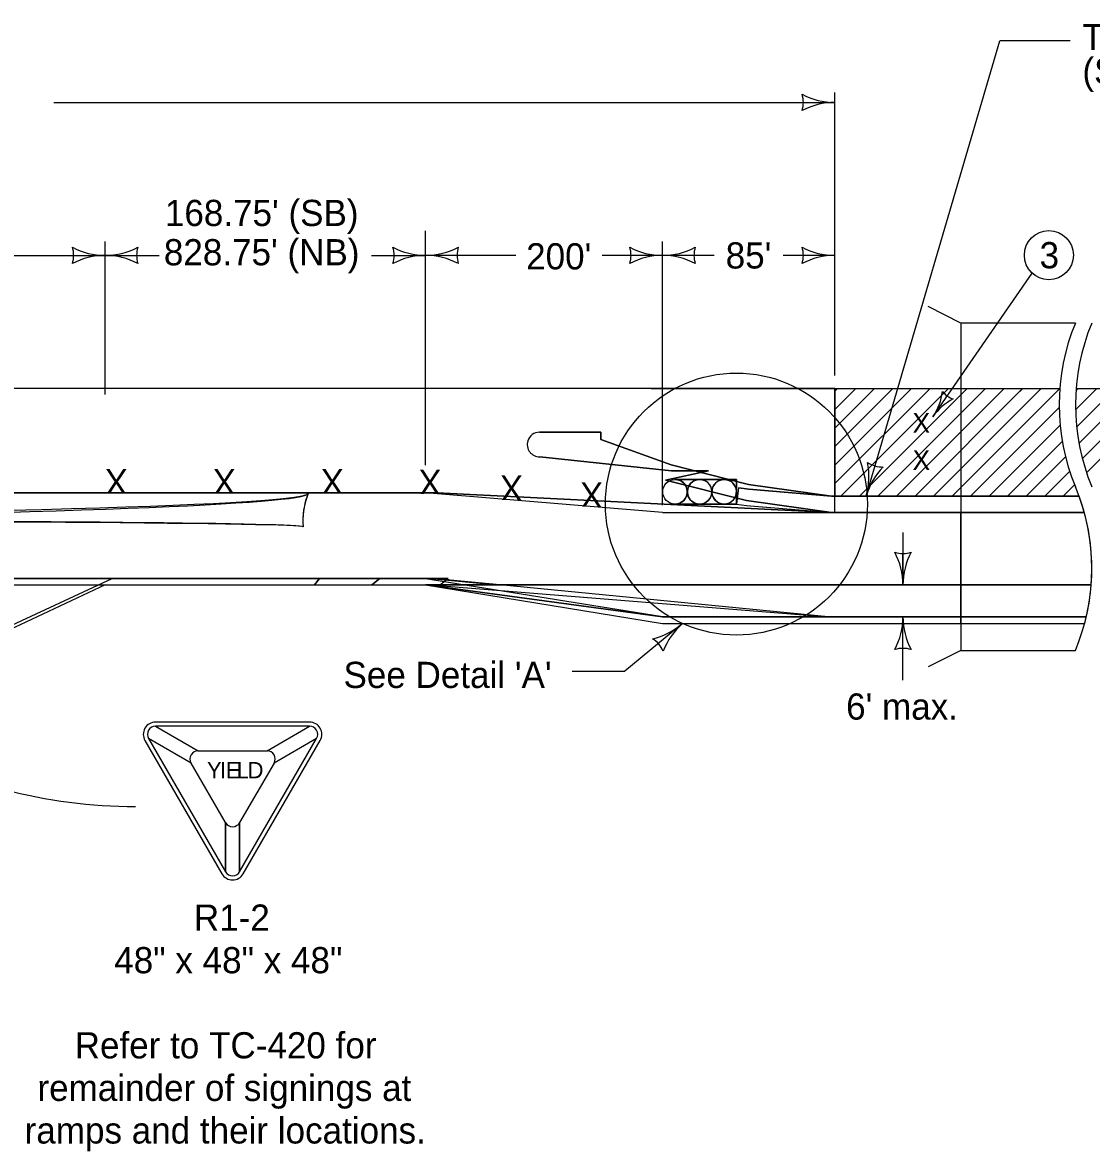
# Model space of a CAD drawing. Extents: x 10134 to 13311, y 7934 to 9733.
# Drawn here: x 12036 to 12689, y 8897 to 9587 of the extents above; entities that cross this region are included whole.
import ezdxf

# ---------------------------------------------------------------- set-up
doc = ezdxf.new("R2010")
doc.units = 0
for name, color, linetype in [('dsnCellElements', 7, 'Continuous'), ('dsnNonPlotable', 7, 'Continuous'), ('dsnstdModifiedBlock', 7, 'Continuous'), ('dsnStdNote', 7, 'Continuous'), ('dsnStdShading', 7, 'Continuous'), ('SheetText', 7, 'Continuous')]:
    doc.layers.add(name, color=color, linetype=linetype)

# ---------------------------------------------------------------- blocks, each defined once
blk = doc.blocks.new('LT')
at = {"layer": 'dsnCellElements'}
for centre, radius, start, end in [((-3.564, 0), 1.642, 342.26665, 17.73335), ((0, 4.25), 4.25, 241.92751, 270), ((0, -4.25), 4.25, 90, 118.07249)]:
    blk.add_arc(centre, radius, start, end, dxfattribs=at)

msp = doc.modelspace()

# ---------------------------------------------------------------- linework, layer by layer
at = {"layer": 'dsnCellElements'}
for p, q in [((12532.42, 9363.04), (12532.42, 9297.31)), ((12532.42, 9316.23), (12579.23, 9363.04)), ((12532.42, 9304.92), (12590.54, 9363.04)), ((12532.42, 9361.48), (12533.97, 9363.04)), ((12532.42, 9350.17), (12545.29, 9363.04)), ((12532.42, 9338.86), (12556.6, 9363.04)), ((12532.42, 9327.54), (12567.91, 9363.04)), ((12536.12, 9297.31), (12601.85, 9363.04)), ((12547.43, 9297.31), (12613.17, 9363.04)), ((12558.75, 9297.31), (12624.48, 9363.04)), ((12570.06, 9297.31), (12635.8, 9363.04)), ((12581.38, 9297.31), (12647.11, 9363.04)), ((12592.69, 9297.31), (12658.42, 9363.04)), ((12643.19, 9359.08), (12647.15, 9363.04)), ((12643.97, 9337.27), (12669.74, 9363.04)), ((12679.39, 9350.06), (12692.36, 9363.04)), ((12679.63, 9361.63), (12681.05, 9363.04)), ((12680.07, 9339.43), (12703.68, 9363.04)), ((12681.49, 9329.54), (12714.99, 9363.04)), ((12683.55, 9320.28), (12726.31, 9363.04)), ((12686.14, 9311.57), (12737.62, 9363.04)), ((12615.32, 9297.31), (12669.36, 9351.36)), ((12604, 9297.31), (12643.97, 9337.27)), ((12626.63, 9297.31), (12669.95, 9340.62)), ((12637.94, 9297.31), (12671.29, 9330.66)), ((12649.26, 9297.31), (12673.28, 9321.33)), ((12660.57, 9297.31), (12675.82, 9312.55)), ((12671.89, 9297.31), (12678.85, 9304.27)), ((12427.15, 9223.54), (12281.29, 9247.02)), ((12211.62, 9159.28), (12117.6, 9159.28)), ((12111.1, 9148.03), (12158.11, 9066.6)), ((12171.1, 9066.6), (12218.11, 9148.03)), ((12160.28, 9097.85), (12160.28, 9067.85)), ((12168.94, 9067.85), (12168.94, 9097.85))]:
    msp.add_line(p, q, dxfattribs=at)
for points in [[(12211.62, 9156.78), (12117.6, 9156.78), (12143.58, 9141.78), (12185.64, 9141.78), (12211.62, 9156.78)], [(12113.27, 9149.28), (12160.28, 9067.85), (12160.28, 9097.85), (12139.25, 9134.28), (12113.27, 9149.28)], [(12168.94, 9067.85), (12215.95, 9149.28), (12189.97, 9134.28), (12168.94, 9097.85), (12168.94, 9067.85)]]:
    msp.add_lwpolyline(points, close=True, dxfattribs=at)
for centre in [(12434.8, 9299.95), (12449.81, 9299.95), (12464.81, 9299.95)]:
    msp.add_circle(centre, 7.5, dxfattribs=at)
for centre, radius, start, end in [((12117.6, 9151.78), 7.5, 90.00021, 209.99992), ((12211.62, 9151.78), 7.5, 330.0002, 89.99991), ((12117.6, 9151.78), 5, 89.99991, 210.00019), ((12117.6, 9151.78), 5, 89.99991, 210.00019), ((12211.62, 9151.78), 5, 330.0002, 89.99991), ((12211.62, 9151.78), 5, 330.0002, 89.99991), ((12143.58, 9136.78), 5, 90.00021, 209.99992), ((12143.58, 9136.78), 5, 90.00021, 209.99992), ((12185.64, 9136.78), 5, 330.0002, 89.99991), ((12185.64, 9136.78), 5, 330.0002, 89.99991), ((12164.61, 9100.35), 5, 209.99992, 330.0002), ((12164.61, 9070.35), 5, 210.00019, 330.00161), ((12164.61, 9070.35), 7.5, 209.99992, 330.0002)]:
    msp.add_arc(centre, radius, start, end, dxfattribs=at)
at = {"layer": 'dsnNonPlotable'}
for p, q in [((12434.8, 9307.45), (12472.31, 9307.45)), ((12472.31, 9307.45), (12472.31, 9292.44)), ((12472.31, 9292.44), (12434.8, 9292.44))]:
    msp.add_line(p, q, dxfattribs=at)
for centre in [(12434.8, 9299.95), (12434.8, 9299.95), (12449.81, 9299.95), (12449.81, 9299.95), (12464.81, 9299.95), (12464.81, 9299.95)]:
    msp.add_circle(centre, 7.5, dxfattribs=at)
at = {"layer": 'dsnstdModifiedBlock'}
for p, q in [((12609.35, 9403.04), (12589.35, 9413.04)), ((11624.65, 9299.31), (12282.39, 9299.31)), ((12427.15, 9287.31), (12282.39, 9299.31)), ((12530.46, 9297.31), (12681.58, 9297.31)), ((12427.15, 9287.31), (12530.46, 9287.31)), ((12684.75, 9287.31), (12530.46, 9287.31)), ((12091.18, 9247.02), (12281.29, 9247.02)), ((12282.49, 9243.04), (12511.31, 9243.04)), ((12511.31, 9243.04), (12688.97, 9243.04)), ((12427.15, 9223.54), (12685.96, 9223.54)), ((12609.35, 9203.04), (12589.35, 9193.04))]:
    msp.add_line(p, q, dxfattribs=at)
for points in [[(12679.35, 9403.04), (12609.35, 9403.04), (12609.35, 9203.04), (12679.35, 9203.04)], [(12473.58, 9302.29), (12472.31, 9292.44), (12472.31, 9292.44)], [(12473.58, 9302.29), (12479.81, 9301.48), (12530.46, 9297.31)], [(12472.31, 9292.44), (12478.54, 9291.64), (12530.46, 9287.31)], [(11663.8, 9047.24), (11864.09, 9141.44), (12091.18, 9247.02)]]:
    msp.add_lwpolyline(points, dxfattribs=at)
for centre, start, end in [((12799.35, 9353.04), 157.38014, 202.61987), ((12809.35, 9353.04), 157.38014, 202.61987), ((12559.35, 9253.04), 337.38014, 22.61987)]:
    msp.add_arc(centre, 130, start, end, dxfattribs=at)
at = {"layer": 'dsnStdNote'}
msp.add_circle((12663.15, 9444.45), 15, dxfattribs=at)
at = {"layer": 'dsnStdShading'}
for p, q in [((12420.28, 9363.04), (11205.92, 9363.04)), ((12420.28, 9363.04), (12669.74, 9363.04)), ((12679.74, 9363.04), (13246.66, 9363.04)), ((12532.42, 9338.86), (12532.42, 9350.17)), ((12389.57, 9331.96), (12389.57, 9336.32)), ((12432.66, 9312.8), (12352.18, 9321.32)), ((12352.18, 9321.32), (12432.66, 9312.8)), ((12532.42, 9304.92), (12532.42, 9316.23)), ((12447.68, 9312.8), (12432.93, 9312.8)), ((12432.93, 9312.8), (12447.68, 9312.8)), ((12455.3, 9312.8), (12447.92, 9312.8)), ((12447.92, 9312.8), (12455.3, 9312.8)), ((12449.42, 9307.46), (12434.82, 9307.46)), ((12464.43, 9307.46), (12449.43, 9307.46)), ((12472.33, 9307.46), (12464.43, 9307.46)), ((12473.58, 9302.29), (12472.31, 9292.44)), ((12472.33, 9300.35), (12472.33, 9307.46)), ((12532.42, 9297.31), (12532.42, 9304.92)), ((11727.95, 9299.31), (12256.6, 9299.31)), ((12289.4, 9299.31), (11727.95, 9299.31)), ((12210.81, 9298.9), (12210.21, 9297.37)), ((12256.61, 9299.31), (12289.4, 9299.31)), ((12289.4, 9299.31), (12530.46, 9287.31)), ((12530.46, 9287.31), (12289.4, 9299.31)), ((12472.33, 9292.46), (12472.33, 9299.96)), ((12681.58, 9297.31), (12530.46, 9297.31)), ((12532.42, 9287.21), (12532.42, 9297.31)), ((12435.21, 9292.46), (12449.78, 9292.46)), ((12450.21, 9292.46), (12465.22, 9292.46)), ((12465.22, 9292.46), (12472.33, 9292.46)), ((12530.46, 9287.31), (12684.75, 9287.31)), ((12609.35, 9287.31), (12530.46, 9287.31)), ((12530.46, 9287.31), (12532.42, 9287.21)), ((12684.75, 9287.31), (12609.35, 9287.31)), ((12609.35, 9287.31), (12609.35, 9243.04)), ((12609.35, 9243.04), (12609.35, 9287.31)), ((12574, 9243.04), (12574, 9262.26)), ((12217.72, 9247.04), (11568.19, 9247.04)), ((12296.26, 9247.04), (11744.13, 9247.04)), ((12214.74, 9243.04), (12217.72, 9247.04)), ((12217.72, 9247.04), (12214.74, 9243.04)), ((12254.54, 9247.04), (12217.72, 9247.04)), ((12254.54, 9247.04), (12249.7, 9243.04)), ((12249.7, 9243.04), (12254.54, 9247.04)), ((12285.31, 9247.02), (12326.47, 9243.04)), ((12327.83, 9243.04), (12286.71, 9247.04)), ((12291.22, 9243.04), (12296.26, 9247.04)), ((11564.95, 9243.04), (12214.74, 9243.04)), ((11741.2, 9243.04), (12291.22, 9243.04)), ((11772.83, 9243.04), (12086.78, 9243.04)), ((12086.78, 9243.04), (11865.15, 9139.17)), ((12214.74, 9243.04), (12249.7, 9243.04)), ((12282.56, 9243.04), (12282.49, 9243.04)), ((12282.49, 9243.04), (12427.15, 9219.54)), ((12282.49, 9243.04), (12427.15, 9219.54)), ((12427.15, 9223.54), (12282.56, 9243.04)), ((12511.31, 9243.04), (12282.56, 9243.04)), ((12282.56, 9243.04), (12427.15, 9223.54)), ((12327.83, 9243.04), (12286.51, 9243.04)), ((12286.51, 9243.04), (12292.82, 9242.43)), ((12292.82, 9242.43), (12528.37, 9223.54)), ((12326.47, 9243.04), (12327.83, 9243.04)), ((12528.37, 9223.54), (12327.83, 9243.04)), ((12327.83, 9243.04), (12511.31, 9243.04)), ((12688.97, 9243.04), (12609.35, 9243.04)), ((12609.35, 9243.04), (12609.35, 9223.54)), ((12609.35, 9243.04), (12688.97, 9243.04)), ((12609.35, 9223.54), (12609.35, 9243.04)), ((12574, 9223.54), (12427.15, 9223.54)), ((12427.15, 9223.54), (12564.19, 9223.54)), ((12427.15, 9219.54), (12684.96, 9219.54)), ((12427.15, 9219.54), (12573.81, 9219.54)), ((12528.38, 9223.54), (12685.96, 9223.54)), ((12564.19, 9223.54), (12574, 9223.54)), ((12582, 9223.54), (12574, 9223.54)), ((12574, 9223.54), (12582, 9223.54)), ((12574.19, 9219.54), (12609.35, 9219.54)), ((12609.35, 9223.54), (12582, 9223.54)), ((12582, 9223.54), (12609.35, 9223.54)), ((12609.35, 9223.54), (12685.96, 9223.54)), ((12609.35, 9219.54), (12609.35, 9223.54)), ((12609.35, 9223.54), (12609.35, 9219.54)), ((12658.62, 9219.54), (12684.96, 9219.54)), ((12659.62, 9223.54), (12685.96, 9223.54))]:
    msp.add_line(p, q, dxfattribs=at)
for points in [[(12532.42, 9363.04), (12492.09, 9363.04), (12420.28, 9363.04)], [(12532.42, 9350.17), (12532.42, 9361.48), (12532.42, 9363.04)], [(12352.06, 9336.32), (12352.06, 9336.32), (12382.06, 9336.32), (12382.09, 9336.32), (12389.57, 9336.32)], [(12389.57, 9336.32), (12382.06, 9336.32), (12352.06, 9336.32)], [(12389.57, 9336.32), (12389.57, 9331.96), (12389.57, 9331.96)], [(12532.42, 9316.23), (12532.42, 9327.54), (12532.42, 9338.86)], [(12389.57, 9331.96), (12432.43, 9316.36), (12479.7, 9304.44), (12530.46, 9297.31), (12532.42, 9297.31)], [(12532.42, 9297.31), (12530.46, 9297.31), (12479.7, 9304.44), (12432.43, 9316.36), (12389.57, 9331.96)], [(12530.46, 9287.31), (12478.52, 9294.56), (12429.01, 9306.97), (12455.3, 9312.8)], [(12455.3, 9312.8), (12429.01, 9306.97), (12478.52, 9294.56), (12530.46, 9287.31)], [(12449.42, 9307.45), (12449.42, 9307.46)], [(12449.43, 9307.46), (12449.43, 9307.45)], [(12464.43, 9307.45), (12464.43, 9307.46)], [(12464.43, 9307.46), (12464.43, 9307.45)], [(12530.46, 9297.31), (12479.81, 9301.48), (12473.58, 9302.29)], [(12210.87, 9298.86), (12210.81, 9298.89)], [(12256.6, 9299.31), (12256.61, 9299.31), (12256.85, 9299.64)], [(12442.31, 9300.35), (12442.33, 9300.35)], [(12457.31, 9300.35), (12457.33, 9300.35)], [(12472.32, 9300.35), (12472.33, 9300.35)], [(12435.21, 9292.47), (12435.21, 9292.46)], [(12450.21, 9292.47), (12450.21, 9292.46)], [(12465.22, 9292.47), (12465.22, 9292.46)], [(12465.22, 9292.46), (12465.22, 9292.47)], [(12472.31, 9292.44), (12478.54, 9291.64), (12530.11, 9287.34), (12530.46, 9287.31)], [(12530.46, 9287.31), (12530.46, 9287.31)], [(11568.18, 9247.02), (12287.26, 9247.02), (12285.31, 9247.02)], [(12286.71, 9247.04), (12285.75, 9247.04), (12254.54, 9247.04)], [(12249.7, 9243.04), (12286.51, 9243.04), (12327.83, 9243.04)], [(12609.35, 9243.04), (12582, 9243.04), (12574, 9243.04), (12563.18, 9243.04), (12511.31, 9243.04)], [(12511.31, 9243.04), (12563.18, 9243.04), (12574, 9243.04)], [(12574, 9243.04), (12582, 9243.04), (12609.35, 9243.04)], [(12685.96, 9223.54), (12659.62, 9223.54), (12609.35, 9223.54)], [(12609.35, 9219.54), (12658.62, 9219.54), (12684.96, 9219.54)]]:
    msp.add_lwpolyline(points, dxfattribs=at)
for centre, radius, start, end in [((12352.06, 9328.82), 7.5, 90, 163.05255), ((12352.06, 9328.82), 7.5, 90, 163.05255), ((12352.06, 9328.82), 7.5, 163.04978, 270.9263), ((12352.06, 9328.82), 7.5, 163.04978, 270.9263), ((12432.79, 9320.3), 7.5, 268.97742, 271.02258), ((12432.79, 9320.3), 7.5, 268.97742, 271.02258), ((12447.8, 9320.3), 7.5, 269.06509, 270.93491), ((12447.8, 9320.3), 7.5, 269.06509, 270.93491), ((12434.82, 9299.96), 7.5, 3.00007, 92.99993), ((12434.82, 9299.96), 7.5, 2.99574, 90), ((12449.82, 9299.96), 7.5, 93.04482, 93), ((12449.82, 9299.96), 7.5, 93.04172, 177.01242), ((12449.82, 9299.96), 7.5, 2.99574, 92.9969), ((12464.83, 9299.96), 7.5, 93.00604, 182.99396), ((12464.82, 9299.96), 7.5, 92.9969, 177.01242), ((12464.81, 9299.95), 7.51, 3.1005, 92.8995), ((12464.82, 9299.96), 7.5, 2.99593, 92.9969), ((12249.03, 9282.49), 41.52, 156.77867, 185.48242), ((12250.01, 9282.47), 42.5, 159.48606, 185.32967), ((12250.01, 9282.47), 42.5, 157.25718, 157.27479), ((12291.19, 9274.6), 42.5, 143.91819, 144.46106), ((12291.19, 9274.6), 42.5, 143.90058, 143.90114), ((12222.52, 9324.68), 42.5, 323.88298, 323.90058), ((12434.79, 9300), 7.55, 273.14031, 356.68109), ((12434.82, 9299.96), 7.5, 273.00246, 317.97075), ((12434.79, 9300), 7.55, 317.82762, 356.66631), ((12449.82, 9299.96), 7.5, 183.01314, 269.67748), ((12449.8, 9300), 7.55, 273.14439, 356.67701), ((12449.82, 9299.96), 7.5, 272.99983, 319.05414), ((12449.8, 9300), 7.55, 318.90204, 356.5996), ((12464.82, 9299.96), 7.5, 182.99578, 273.00422), ((12464.82, 9299.96), 7.5, 183.08128, 273.00246), ((12464.82, 9299.96), 7.5, 272.99981, 3.00019), ((12464.82, 9299.96), 7.5, 273.00246, 0), ((12559.35, 9253.04), 130, 15.28231, 19.90723), ((12559.35, 9253.04), 130, 355.58827, 15.28231), ((12574, 9278.68), 16.42, 252.26665, 270), ((12531.5, 9243.04), 42.5, 0.0176, 28.07249), ((12616.5, 9243.04), 42.5, 179.9824, 180), ((12559.35, 9253.04), 130, 346.88165, 355.58827), ((12531.5, 9223.54), 42.5, 354.59945, 360), ((12531.5, 9223.54), 42.5, 359.9824, 360), ((12616.5, 9223.54), 42.5, 180.0176, 185.40055), ((12559.35, 9253.04), 130, 345.06444, 346.88165)]:
    msp.add_arc(centre, radius, start, end, dxfattribs=at)
for centre, major_axis, ratio, start_param, end_param in [((6684.68, 9331.8), (5526.17, -32.74), 0.008175, 5.82835, 6.279465), ((8654.55, 9315.33), (3556.3, -16.26), 0.011041, 5.788962, 6.278612), ((9235.16, 9266.84), (2972.56, 11.64), 0.003601, 0.004187, 0.623197), ((9969.76, 9266.04), (2237.97, 12.43), 0.004792, 0.005553, 0.624564)]:
    msp.add_ellipse(centre, major_axis=major_axis, ratio=ratio, start_param=start_param, end_param=end_param, dxfattribs=at)
at = {"layer": 'SheetText'}
for p, q in [((12551.5, 9297.31), (12633.26, 9575.35)), ((12676.11, 9575.35), (12633.26, 9575.35)), ((12532.42, 9371.04), (12532.42, 9543.8)), ((12055.42, 9537.75), (12532.42, 9537.75)), ((12282.49, 9316.27), (12282.49, 9459.3)), ((12086.78, 9359.32), (12086.78, 9452.84)), ((12427.15, 9291.86), (12427.15, 9452.84)), ((11980.12, 9444.33), (12086.78, 9444.33)), ((12086.78, 9444.33), (12119.78, 9444.33)), ((12249.49, 9444.33), (12282.49, 9444.33)), ((12337.66, 9444.33), (12282.49, 9444.33)), ((12427.15, 9444.32), (12390.35, 9444.33)), ((12458.72, 9444.32), (12427.15, 9444.32)), ((12532.42, 9444.32), (12500.85, 9444.32)), ((12592.32, 9345.78), (12653, 9433.41)), ((12574, 9275.04), (12574, 9243.04)), ((12563.18, 9243.04), (12582, 9243.04)), ((12439.41, 9219.52), (12404.07, 9190.32)), ((12564.19, 9223.54), (12582, 9223.54)), ((12574, 9184.78), (12574, 9223.54)), ((12372.07, 9190.32), (12404.07, 9190.32))]:
    msp.add_line(p, q, dxfattribs=at)
msp.add_circle((12472.31, 9292.44), 80, dxfattribs=at)
for centre, radius, start, end in [((12496.78, 9537.75), 16.42, 342.26665, 17.73335), ((12532.42, 9580.25), 42.5, 241.92751, 270), ((12532.42, 9495.25), 42.5, 90, 118.07249), ((12051.15, 9444.32), 16.42, 342.26665, 17.73335), ((12086.78, 9486.82), 42.5, 241.92751, 270), ((12086.78, 9486.82), 42.5, 270, 298.07249), ((12122.42, 9444.32), 16.42, 162.26665, 197.73335), ((12246.85, 9444.33), 16.42, 342.26665, 17.73335), ((12282.49, 9486.83), 42.5, 241.92751, 270), ((12282.49, 9486.83), 42.5, 270, 298.07249), ((12318.12, 9444.33), 16.42, 162.26665, 197.73335), ((12391.51, 9444.32), 16.42, 342.26665, 17.73335), ((12427.15, 9486.82), 42.5, 241.92751, 270), ((12427.15, 9486.82), 42.5, 270, 298.07249), ((12462.79, 9444.32), 16.42, 162.26665, 197.73335), ((12496.78, 9444.32), 16.42, 342.26665, 17.73335), ((12532.42, 9486.82), 42.5, 241.92751, 270), ((12086.78, 9401.82), 42.5, 90, 118.07249), ((12086.78, 9401.82), 42.5, 61.92751, 90), ((12282.49, 9401.83), 42.5, 90, 118.07249), ((12282.49, 9401.83), 42.5, 61.92751, 90), ((12427.15, 9401.82), 42.5, 90, 118.07249), ((12427.15, 9401.82), 42.5, 61.92751, 90), ((12532.42, 9401.82), 42.5, 90, 118.07249), ((12510.73, 9309.3), 42.5, 343.61306, 11.68555), ((12561.56, 9331.5), 16.42, 235.87971, 271.34641), ((12592.28, 9285.32), 42.5, 135.54057, 163.61306), ((12574, 9278.68), 16.42, 252.26665, 287.73335), ((12531.5, 9243.04), 42.5, 360, 28.07249), ((12616.5, 9243.04), 42.5, 151.92751, 180), ((12411.5, 9251.58), 42.5, 282.97403, 311.04652), ((12467.32, 9187.47), 42.5, 131.04652, 159.11901), ((12531.5, 9223.54), 42.5, 331.92751, 360), ((12616.5, 9223.54), 42.5, 180, 208.07249), ((12412.53, 9196.12), 16.42, 23.31317, 58.77987), ((12574, 9187.9), 16.42, 72.26665, 107.73335), ((12104.69, 9412.41), 304.74, 239.62403, 270.12763)]:
    msp.add_arc(centre, radius, start, end, dxfattribs=at)

# ---------------------------------------------------------------- block references
at = {"layer": 'SheetText', "xscale": 7.999600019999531, "yscale": 7.999200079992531, "rotation": -124.70293665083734}
msp.add_blockref('LT', (12592.32, 9345.78), dxfattribs=at)

# ---------------------------------------------------------------- texts
at = {"layer": 'dsnCellElements'}
for s, height, p in [('X', 12, (12579.87, 9335.97)), ('X', 12, (12579.87, 9313.32)), ('Y', 10, (12148.99, 9124.9)), ('I', 10, (12156.93, 9124.9)), ('E', 10, (12160.44, 9124.9)), ('L', 10, (12167.13, 9124.9)), ('D', 10, (12173.82, 9124.9))]:
    msp.add_text(s, height=height, dxfattribs=at).set_placement(p)
for p in [(12100.35, 9313.89), (12166.31, 9313.89), (12232.27, 9313.89), (12291.92, 9313.55), (12341.67, 9310.02), (12390.6, 9305.79)]:
    msp.add_text('X', height=15, rotation=180, dxfattribs=at).set_placement(p)
at = {"layer": 'dsnStdNote'}
msp.add_text('3', height=16, dxfattribs=at).set_placement((12657.45, 9436.45))
at = {"layer": 'SheetText'}
for s, p in [('Temporary Barrier Rail', (12683.58, 9569.7)), ('(See Typical ', (12683.58, 9548.99)), ("168.75' (SB)", (12123.27, 9462.27)), ("828.75' (NB)", (12122.66, 9438.27)), ("200'", (12343.9, 9435.77)), ("85'", (12465.75, 9436.32)), ("See Detail 'A'", (12232.35, 9180.1)), ("6' max.", (12539.3, 9160.78)), ('R1-2', (12140.98, 9031.85)), ('48" x 48" x 48"', (12092.34, 9005.85)), ('Refer to TC-420 for', (12068.2, 8953.85)), ('remainder of signings at', (12045.45, 8927.85)), ('ramps and their locations.', (12037.64, 8901.85))]:
    msp.add_text(s, height=16, dxfattribs=at).set_placement(p)

doc.saveas('drawing.dxf')
